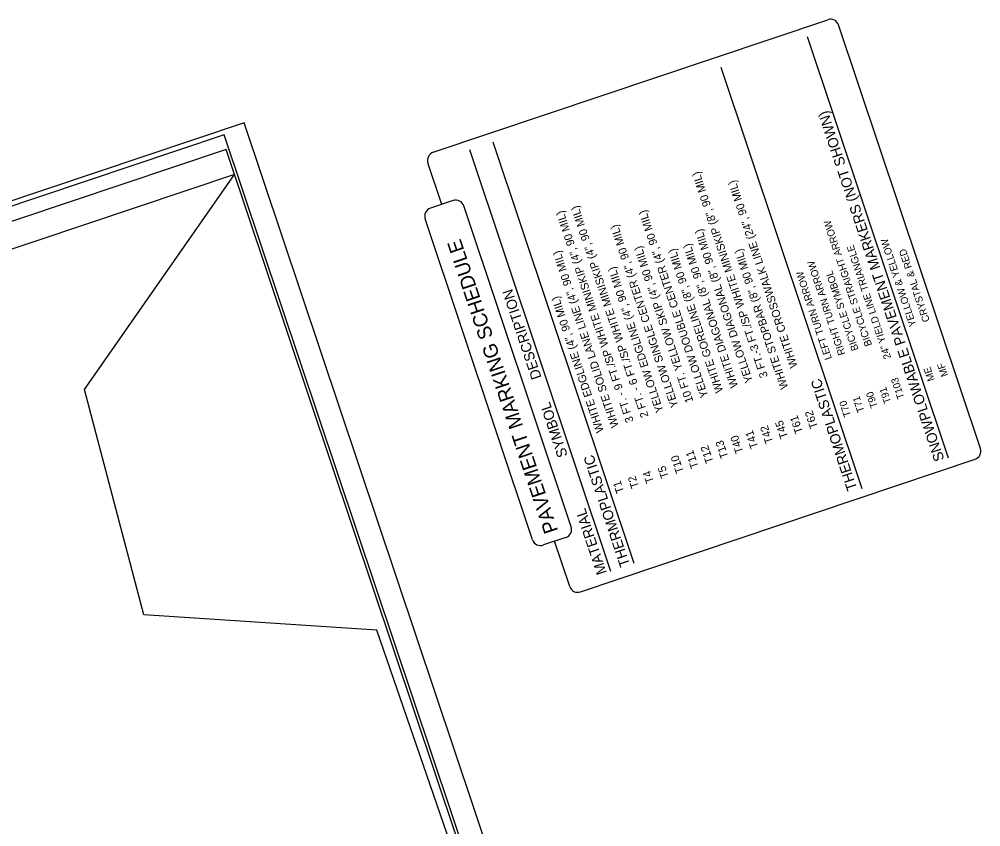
# Model space of a CAD drawing. Extents: x 1615436 to 1617119, y 903110 to 905145.
# Drawn here: x 1616278 to 1617119, y 904439 to 905145 of the extents above; entities that cross this region are included whole.
import ezdxf

# ---------------------------------------------------------------- set-up
doc = ezdxf.new("R2010")
doc.units = 0
for name, color, linetype in [('DEV BORDER CELL', 7, 'Continuous'), ('Gray Area Fill Shapes', 7, 'Continuous'), ('Sheet Layout Plan Border', 7, 'Continuous'), ('Sheet Plan CELL', 7, 'Continuous'), ('Sheet Plot Border Inside CELL', 7, 'Continuous'), ('Sheet Plot Border Outside CELL', 7, 'Continuous'), ('Sheet Title CELL', 7, 'Continuous')]:
    doc.layers.add(name, color=color, linetype=linetype)

msp = doc.modelspace()

# ---------------------------------------------------------------- linework, layer by layer
at = {"layer": 'DEV BORDER CELL'}
for p, q in [((1617090.67, 904761.54), (1616967.33, 905129.89)), ((1617015.26, 904734.73), (1616891.92, 905103.08)), ((1616815.62, 904669.34), (1616692.25, 905037.79)), ((1616795.24, 904662.52), (1616671.87, 905030.97))]:
    msp.add_line(p, q, dxfattribs=at)
at = {"layer": 'Sheet Layout Plan Border'}
msp.add_lwpolyline([(1616672.58, 903656.2), (1616919.77, 903656.8), (1616590.65, 904611.24), (1616386.84, 904624.44), (1616334.81, 904821.64), (1616466, 905009.57), (1615641.09, 904732.87), (1615700.02, 904557.19), (1615560.35, 904510.33), (1615954.19, 903336.21)], close=True, dxfattribs=at)
at = {"layer": 'Sheet Plan CELL'}
msp.add_lwpolyline([(1615463.14, 904697.64), (1615940.18, 903275.48), (1616935.67, 903609.4), (1616458.64, 905031.54)], close=True, dxfattribs=at)
at = {"layer": 'Sheet Plot Border Inside CELL'}
msp.add_lwpolyline([(1616986.86, 903464.68), (1616457.04, 905044.17), (1615456.82, 904708.68), (1615986.63, 903129.17)], close=True, dxfattribs=at)
at = {"layer": 'Sheet Plot Border Outside CELL'}
msp.add_lwpolyline([(1617009.96, 903458.71), (1616474.57, 905054.81), (1615436.42, 904706.58), (1615971.81, 903110.48)], close=True, dxfattribs=at)
at = {"layer": 'Sheet Title CELL'}
for p, q in [((1616639.9, 905028.98), (1616985.22, 905144.92)), ((1617118.58, 904769.82), (1616994.54, 905140.27)), ((1616647.42, 904983.31), (1616635.25, 905019.66)), ((1616657.41, 904986.68), (1616637.43, 904979.99)), ((1616760.64, 904701.57), (1616666.73, 904982.04)), ((1616726.7, 904690.19), (1616632.79, 904970.67)), ((1616768.68, 904644.58), (1617113.94, 904760.5)), ((1616756, 904692.25), (1616736.4, 904685.69)), ((1616759.36, 904649.22), (1616746.07, 904688.92))]:
    msp.add_line(p, q, dxfattribs=at)
for centre, start, end in [((1616987.56, 905137.94), 18.51236, 108.51236), ((1616642.23, 905022), 108.51236, 198.51236), ((1616659.75, 904979.7), 18.5425, 108.5425), ((1616639.77, 904973.01), 108.48222, 198.5425), ((1617111.6, 904767.48), 288.51236, 18.51236), ((1616753.66, 904699.23), 288.5425, 18.5425), ((1616733.68, 904692.53), 198.5425, 291.6591), ((1616766.34, 904651.56), 198.51236, 288.51236)]:
    msp.add_arc(centre, 7.36, start, end, dxfattribs=at)

# ---------------------------------------------------------------- texts
at = {"layer": 'DEV BORDER CELL'}
for s, height, rotation, p in [('SNOWPLOWABLE PAVEMENT MARKERS (NOT SHOWN)', 9, 108.50298, (1617087.25, 904760.4)), ('3 FT.-3 FT./SP WHITE MINISKIP (8", 90 MIL)', 7, 108.44558, (1616932.76, 904833.03)), ('WHITE CROSSWALK LINE (24", 90 MIL)', 7, 108.44558, (1616958.84, 904841.73)), ('2 FT. - 6 FT./SP WHITE MINISKIP (4", 90 MIL)', 7, 108.44558, (1616828.44, 904798.24)), ('YELLOW DOUBLE CENTER (4", 90 MIL)', 7, 108.44558, (1616880.6, 904815.64)), ('3 FT. - 9 FT./SP WHITE MINISKIP (4", 90 MIL)', 7, 108.44558, (1616815.4, 904793.89)), ('YELLOW SINGLE CENTER (4", 90 MIL)', 7, 108.44558, (1616854.52, 904806.94)), ('YELLOW DIAGONAL (8", 90 MIL)', 7, 108.44558, (1616919.72, 904828.68)), (' BICYCLE STRAIGHT ARROW', 6.3, 108.47217, (1617024.64, 904858.25)), ('YELLOW & YELLOW', 6.3, 108.50298, (1617062.72, 904877.75)), ('10 FT. YELLOW SKIP (4", 90 MIL)', 7, 108.44558, (1616867.56, 904811.29)), ('WHITE GORELINE (8", 90 MIL)', 7, 108.44558, (1616893.64, 904819.98)), ('WHITE DIAGONAL (8", 90 MIL)', 7, 108.44558, (1616906.68, 904824.33)), ('     WHITE STOPBAR (8", 90 MIL)', 7, 108.44558, (1616954.66, 904810.82)), ('     24" YIELD LINE TRIANGLE', 6.3, 108.47217, (1617044.32, 904838.25)), ('CRYSTAL & RED', 6.3, 108.50298, (1617074.45, 904881.68)), ('WHITE SOLID LANE LINE (4", 90 MIL)', 7, 108.44558, (1616802.36, 904789.54)), ('YELLOW EDGLINE (4", 90 MIL)', 7, 108.44558, (1616841.48, 904802.59)), (' RIGHT TURN ARROW', 6.3, 108.47217, (1617001.25, 904850.43)), (' LEFT TURN ARROW', 6.3, 108.47217, (1616989.55, 904846.53)), (' BICYCLE SYMBOL', 6.3, 108.47217, (1617012.94, 904854.34)), ('DESCRIPTION', 9, 108.47216, (1616734.8, 904832.11)), ('WHITE EDGLINE (4", 90 MIL)', 7, 108.44558, (1616789.32, 904785.19)), ('MF', 6.3, 108.50298, (1617090.45, 904833.89)), ('ME', 6.3, 108.50298, (1617078.71, 904829.96)), ('THERMOPLASTIC', 9, 108.47216, (1617011.01, 904734.86)), ('T103', 6.3, 108.47217, (1617052.3, 904814.35)), ('T90', 6.3, 108.47217, (1617028.91, 904806.54)), ('T91', 6.3, 108.47217, (1617040.61, 904810.44)), ('SYMBOL', 9, 108.47216, (1616757.61, 904763.82)), ('T70', 6.3, 108.47217, (1617005.52, 904798.72)), ('T71', 6.3, 108.47217, (1617017.22, 904802.63)), ('T62', 7, 108.44558, (1616976.55, 904788.61)), ('T45', 7, 108.44558, (1616950.47, 904779.91)), ('T61', 7, 108.44558, (1616963.51, 904784.26)), ('T41', 7, 108.44558, (1616924.4, 904771.21)), ('T42', 7, 108.44558, (1616937.44, 904775.56)), ('T13', 7, 108.44558, (1616898.32, 904762.51)), ('T40', 7, 108.44558, (1616911.36, 904766.86)), ('T11', 7, 108.44558, (1616872.24, 904753.81)), ('T12', 7, 108.44558, (1616885.28, 904758.16)), ('THERMOPLASTIC', 9, 108.47216, (1616812.21, 904668.2)), ('T10', 7, 108.44558, (1616859.2, 904749.46)), ('T5', 7, 108.44558, (1616846.16, 904745.12)), ('T2', 7, 108.44558, (1616820.08, 904736.42)), ('T4', 7, 108.44558, (1616833.12, 904740.77)), ('T1', 7, 108.44558, (1616807.04, 904732.07)), ('MATERIAL', 9, 108.47216, (1616791.83, 904661.38))]:
    msp.add_text(s, height=height, rotation=rotation, dxfattribs=at).set_placement(p)
at = {"layer": 'Gray Area Fill Shapes'}
msp.add_text('PAVEMENT MARKING SCHEDULE', height=12.4795, rotation=108.51236, dxfattribs=at).set_placement((1616749.37, 904698.08))

doc.saveas('drawing.dxf')
